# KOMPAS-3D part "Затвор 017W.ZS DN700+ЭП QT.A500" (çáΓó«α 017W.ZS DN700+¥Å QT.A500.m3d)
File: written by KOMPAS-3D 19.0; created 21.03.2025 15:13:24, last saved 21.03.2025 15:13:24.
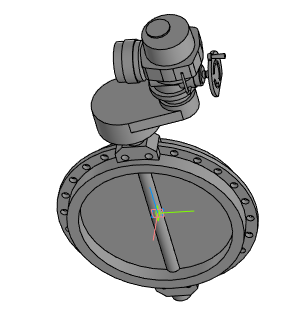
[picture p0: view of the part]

Document properties: Полное имя файла: Затвор 017W.ZS DN700+ЭП QT.A500.a3d

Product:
- Part/product: Затвор 017W.ZS DN700+ЭП QT.A500
    Масса: 553.824

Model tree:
1. Операция без истории:1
